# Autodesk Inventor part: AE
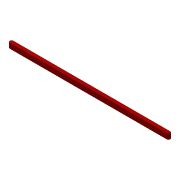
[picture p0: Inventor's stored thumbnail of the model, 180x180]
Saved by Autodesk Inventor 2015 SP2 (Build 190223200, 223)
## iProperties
Created: 2019-08
Part Number: AE
Material: 一般
Document SubType Name: Modeling
Designer: Kuan_Lun Hsu
Density: 1 g/cm^3
Appearance: 平滑 - 紅色
Mass: 0.549425 g
Surface Area: 9.25133 cm^2
Volume: 0.549425 cm^3
Author: Kuan_Lun Hsu
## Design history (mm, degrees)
sketch "草圖1"
  geometry: L1 (0, 0)-(90, 0); L2 (0, -1)-(90, -1); L3 (90, 1)-(0, 1); A1 r 1 centre (0, 0) between (0, 1) and (0, -1); A2 r 1 centre (90, 0) between (90, -1) and (90, 1); 1 further point
  constraints: 8 end point, 4 point on circle, 4 tangent, 2 centre point, 1 horizontal, 1 midpoint, 1 parallel
  dimensions: "d0" = 90 distance of L1.start L1.end (= AE_); "d1" = 2 distance between parallel lines of L2 L3 (= w_)
extrude "擠出1" new body sketch "草圖1" distance "d2" = 1 (= t_); taper "d3" = 0 deg
node "實體1"
other parameters: "AE_" = 90 [user parameter; used in 1 equation term], "w_" = 2 [user parameter; used in 1 equation term], "t_" = 1 [user parameter; used in 1 equation term]
